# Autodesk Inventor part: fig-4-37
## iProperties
Created: 2005-12
Part Number: fig-4-37
Document SubType Name: Modeling
Designer: CADCIM
Density: 1 g/cm^3
Author: CADCIM
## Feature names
1. Extrusion1
